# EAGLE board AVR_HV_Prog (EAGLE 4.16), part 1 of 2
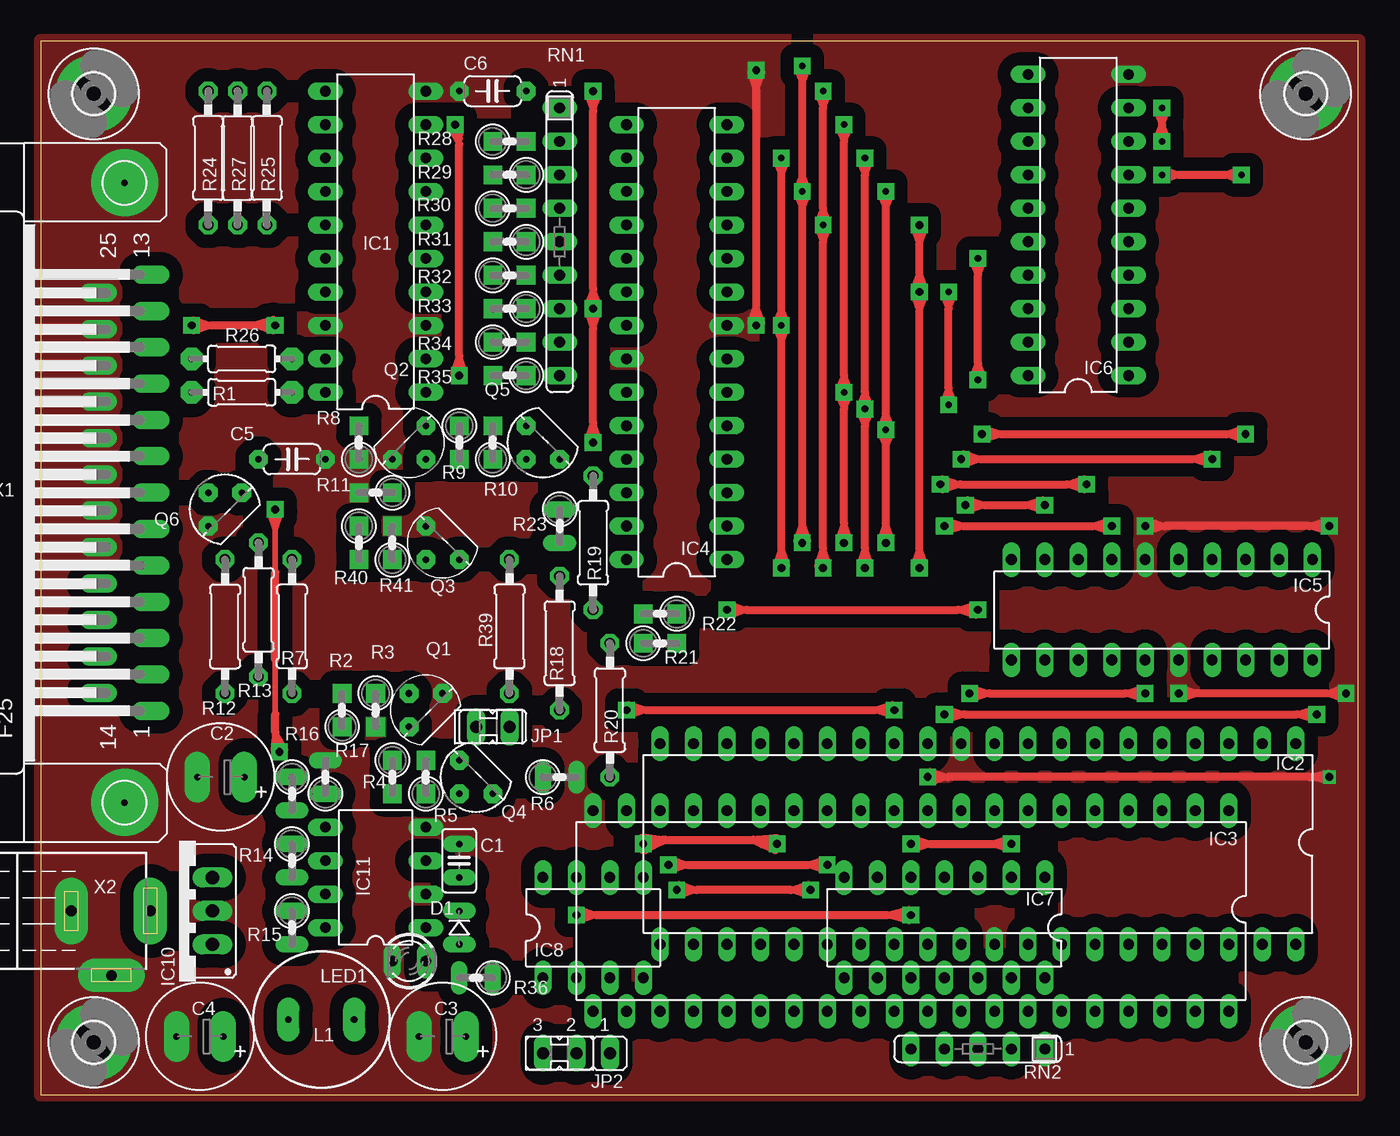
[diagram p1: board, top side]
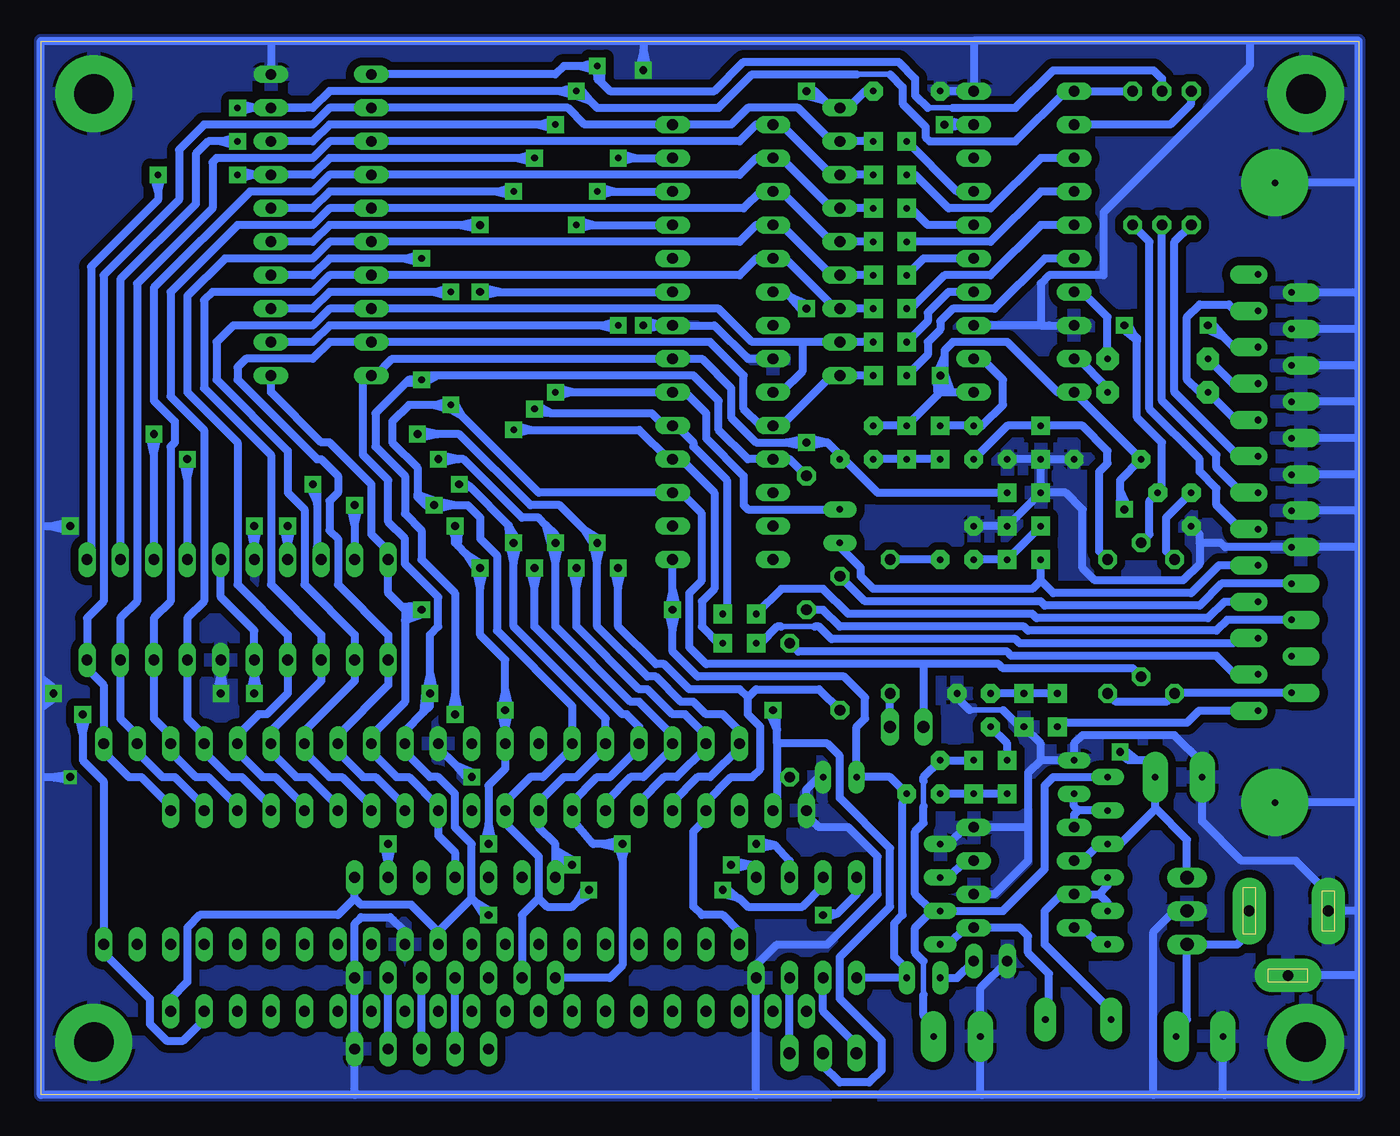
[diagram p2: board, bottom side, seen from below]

Size 100 x 80 mm. Coordinates in mm from the lower left corner, seen from the top.
Outline: 0,0 100,0 100,80 0,80 0,0
Copper layers (1*16): Top 0.035mm / dielectric 1.5mm / Bottom 0.035mm
Design rules "default": minimum track width 12mil, minimum drill 10mil, track to track 10mil, track to pad 12mil, pad to pad 12mil, via to via 12mil, smd to smd 8mil, copper to edge 0mil, drill to drill 8mil, minimum pad ring 10mil, minimum via ring 8mil, stop-mask expansion 4mil, vias tented up to drill 0mil, thermal gap 10mil

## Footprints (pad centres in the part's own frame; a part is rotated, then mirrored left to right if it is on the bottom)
C025-025X050 = drill 0.5 pad 1.27 long: 1 -1.27,0; 2 1.27,0
E3,5-8 = drill 0.5 pad 1.93 long: + -1.778,0; - 1.778,0
C050-024X044 = drill 0.5 pad 1.422 octagon: 1 -2.54,0; 2 2.54,0
D-2.5 = drill 0.5 pad 1.27 long: A 1.27,0; C -1.27,0
3,0-PAD = drill 3 pad 5.842 round: B3,0 0,0
DIL20 = drill 0.813 long: 1 -11.43,-3.81; 2 -8.89,-3.81; 3 -6.35,-3.81; 4 -3.81,-3.81; 5 -1.27,-3.81; 6 1.27,-3.81; 7 3.81,-3.81; 8 6.35,-3.81; 9 8.89,-3.81; 10 11.43,-3.81; 11 11.43,3.81; 12 8.89,3.81; 13 6.35,3.81; 14 3.81,3.81; 15 1.27,3.81; 16 -1.27,3.81; 17 -3.81,3.81; 18 -6.35,3.81; 19 -8.89,3.81; 20 -11.43,3.81
DIL40 = drill 0.813 long: 1 -24.13,-7.62; 2 -21.59,-7.62; 3 -19.05,-7.62; 4 -16.51,-7.62; 5 -13.97,-7.62; 6 -11.43,-7.62; 7 -8.89,-7.62; 8 -6.35,-7.62; 9 -3.81,-7.62; 10 -1.27,-7.62; 11 1.27,-7.62; 12 3.81,-7.62; 13 6.35,-7.62; 14 8.89,-7.62; 15 11.43,-7.62; 16 13.97,-7.62; 17 16.51,-7.62; 18 19.05,-7.62; 19 21.59,-7.62; 20 24.13,-7.62; 21 24.13,7.62; 22 21.59,7.62; 23 19.05,7.62; 24 16.51,7.62; 25 13.97,7.62; 26 11.43,7.62; 27 8.89,7.62; 28 6.35,7.62; 29 3.81,7.62; 30 1.27,7.62; 31 -1.27,7.62; 32 -3.81,7.62; 33 -6.35,7.62; 34 -8.89,7.62; 35 -11.43,7.62; 36 -13.97,7.62; 37 -16.51,7.62; 38 -19.05,7.62; 39 -21.59,7.62; 40 -24.13,7.62
DIL28-3 = drill 0.813 long: 1 -16.51,-3.81; 2 -13.97,-3.81; 3 -11.43,-3.81; 4 -8.89,-3.81; 5 -6.35,-3.81; 6 -3.81,-3.81; 7 -1.27,-3.81; 8 1.27,-3.81; 9 3.81,-3.81; 10 6.35,-3.81; 11 8.89,-3.81; 12 11.43,-3.81; 13 13.97,-3.81; 14 16.51,-3.81; 15 16.51,3.81; 16 13.97,3.81; 17 11.43,3.81; 18 8.89,3.81; 19 6.35,3.81; 20 3.81,3.81; 21 1.27,3.81; 22 -1.27,3.81; 23 -3.81,3.81; 24 -6.35,3.81; 25 -8.89,3.81; 26 -11.43,3.81; 27 -13.97,3.81; 28 -16.51,3.81
DIL14 = drill 0.813 long: 1 -7.62,-3.81; 2 -5.08,-3.81; 3 -2.54,-3.81; 4 0,-3.81; 5 2.54,-3.81; 6 5.08,-3.81; 7 7.62,-3.81; 8 7.62,3.81; 9 5.08,3.81; 10 2.54,3.81; 11 0,3.81; 12 -2.54,3.81; 13 -5.08,3.81; 14 -7.62,3.81
DIL08 = drill 0.813 long: 1 -3.81,-3.81; 2 -1.27,-3.81; 3 1.27,-3.81; 4 3.81,-3.81; 5 3.81,3.81; 6 1.27,3.81; 7 -1.27,3.81; 8 -3.81,3.81
78XXS = drill 1.016 long: GND 0,-2.54; IN -2.54,-2.54; OUT 2.54,-2.54
DIL-08 = drill 0.813 long: 1 -3.81,-3.81; 2 -1.27,-3.81; 3 1.27,-3.81; 4 3.81,-3.81; 5 3.81,3.81; 6 1.27,3.81; 7 -1.27,3.81; 8 -3.81,3.81
JP1 = drill 0.914 long: 1 0,-1.27; 2 0,1.27
JP2 = drill 0.914 long: 1 -2.54,0; 2 0,0; 3 2.54,0
BS11 = drill 0.5 pad 1.676 long: 1 -2.5,0; 2 2.5,0
LED3MM = drill 0.813 pad 1.27 long: A -1.27,0; K 1.27,0
TO92 = drill 0.5 pad 1.422 octagon: 1 1.27,1.27; 2 -1.27,1.27; 3 -1.27,-1.27
0204/7 = drill 0.5 pad 1.676 octagon: 1 -3.81,0; 2 3.81,0
0207/2V = drill 0.5 pad 1.422 square: 1 -1.27,0; 2 1.27,0
0207V = drill 0.5 pad 1.27 long: 1 -1.27,0; 2 1.27,0
0207/10 = drill 0.813 pad 1.422 octagon: 1 -5.08,0; 2 5.08,0
SIL9 = drill 0.813 long: 1 -10.16,0; 2 -7.62,0; 3 -5.08,0; 4 -2.54,0; 5 0,0; 6 2.54,0; 7 5.08,0; 8 7.62,0; 9 10.16,0
SIL5 = drill 0.813 long: 1 -5.08,0; 2 -2.54,0; 3 0,0; 4 2.54,0; 5 5.08,0
F25HP = drill 0.5 pad 1.422 offset: 1 -16.561,-1.27; 2 -13.792,-1.27; 3 -11.049,-1.27; 4 -8.28,-1.27; 5 -5.512,-1.27; 6 -2.769,-1.27; 7 0,-1.27; 8 2.769,-1.27; 9 5.512,-1.27; 10 8.28,-1.27; 11 11.049,-1.27; 12 13.792,-1.27; 13 16.561,-1.27; 14 -15.189,1.27; 15 -12.421,1.27; 16 -9.652,1.27; 17 -6.909,1.27; 18 -4.14,1.27; 19 -1.372,1.27; 20 1.372,1.27; 21 4.14,1.27; 22 6.909,1.27; 23 9.652,1.27; 24 12.421,1.27; 25 15.189,1.27 | drill 0.5 pad 5.08 round: G1 -23.52,0; G2 23.52,0
NEB21R = drill 0.813 pad 2.54 long: + 0,7.35; - 0,1.35; C 4.9,4.4

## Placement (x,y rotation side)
C1  1nF  [C025-025X050]  31.75,17.78 90 top
C2  330µ16V  [E3,5-8]  13.65,24.13 180 top
C3  220µ25V  [E3,5-8]  30.48,4.45 180 top
C4  220µ25V  [E3,5-8]  12.06,4.45 180 top
C5  100n  [C050-024X044]  19.05,48.26 0 top
C6  10n  [C050-024X044]  34.29,76.2 180 top
D1  SB120  [D-2.5]  31.75,12.7 270 top
H1  MOUNT-PAD-ROUND3.0  [3,0-PAD]  4,76 0 top
H2  MOUNT-PAD-ROUND3.0  [3,0-PAD]  4,4 0 top
H3  MOUNT-PAD-ROUND3.0  [3,0-PAD]  96,4 0 top
H4  MOUNT-PAD-ROUND3.0  [3,0-PAD]  96,76 0 top
IC1  74HC299N  [DIL20]  25.4,64.77 90 top
IC2  [DIL40]  71.12,19.05 180 top
IC3  [DIL40]  66.04,13.97 180 top
IC4  [DIL28-3]  48.26,57.15 90 top
IC5  [DIL20]  85.09,36.83 180 top
IC6  [DIL20]  78.74,66.04 90 top
IC7  [DIL14]  68.58,12.7 180 top
IC8  [DIL08]  41.91,12.7 0 top
IC10  LM2940-5  [78XXS]  10.48,13.97 90 top
IC11  MC34063AP  [DIL-08]  25.4,16.51 90 top
J1  [JUMP]  33.97,27.94 90 top
J2  [JUMP]  39.37,3.17 90 top
JP1  DIP8/14  [JP1]  34.29,27.94 270 top
JP2  [JP2]  40.64,3.17 180 top
L1  330µH  [BS11]  21.27,5.71 0 top
LED1  [LED3MM]  27.94,10.16 180 top
Q1  BC547  [TO92]  29.21,29.21 0 top
Q2  BC547  [TO92]  27.94,49.53 180 top
Q3  BC547  [TO92]  30.48,41.91 90 top
Q4  BC557  [TO92]  33.02,24.13 90 top
Q5  BC557  [TO92]  38.1,49.53 90 top
Q6  BC557  [TO92]  13.97,44.45 0 top
R1  1k  [0204/7]  15.24,53.34 180 top
R2  10k  [0207/2V]  22.86,29.21 90 top
R3  10k  [0207/2V]  25.4,29.21 270 top
R4  10k  [0207/2V]  26.67,24.13 270 top
R5  10k  [0207/2V]  29.21,24.13 90 top
R6  4k7  [0207V]  39.37,24.13 0 top
R7  10k  [0207/10]  19.05,35.56 90 top
R8  10k  [0207/2V]  24.13,49.53 90 top
R9  2k2  [0207/2V]  31.75,49.53 270 top
R10  47k  [0207/2V]  34.29,49.53 90 top
R11  680R  [0207/2V]  25.4,45.72 180 top
R12  10k  [0207/10]  13.97,35.56 270 top
R13  100R  [0207/10]  16.51,36.83 270 top
R14  0R22  [0207V]  19.05,17.78 270 top
R15  180R  [0207V]  19.05,12.7 270 top
R16  24k  [0207V]  19.05,22.86 270 top
R17  2k7  [0207V]  21.59,24.13 90 top
R18  1k  [0207/10]  39.37,34.29 270 top
R19  1k  [0207/10]  41.91,41.91 90 top
R20  1k  [0207/10]  43.18,29.21 270 top
R21  1k  [0207/2V]  46.99,34.29 0 top
R22  1k  [0207/2V]  46.99,36.51 180 top
R23  1k  [0207V]  39.37,43.18 270 top
R24  1k  [0207/10]  12.7,71.12 90 top
R25  1k  [0207/10]  17.14,71.12 90 top
R26  100R  [0204/7]  15.24,55.88 0 top
R27  1k  [0207/10]  14.92,71.12 270 top
R28  1k  [0207/2V]  35.56,72.39 0 top
R29  1k  [0207/2V]  35.56,69.85 180 top
R30  1k  [0207/2V]  35.56,67.31 0 top
R31  1k  [0207/2V]  35.56,64.77 180 top
R32  1k  [0207/2V]  35.56,62.23 0 top
R33  1k  [0207/2V]  35.56,59.69 180 top
R34  1k  [0207/2V]  35.56,57.15 0 top
R35  1k  [0207/2V]  35.56,54.61 180 top
R36  4k7  [0207V]  33.02,8.89 180 top
R39  100R  [0207/10]  35.56,35.56 90 top
R40  10k  [0207/2V]  24.13,41.91 270 top
R41  10k  [0207/2V]  26.67,41.91 90 top
RN1  100k  [SIL9]  39.37,64.77 270 top
RN2  4*1k  [SIL5]  71.12,3.49 180 top
X1  [F25HP]  6.35,45.72 90 top
X2  +6...24V  [NEB21R]  0.95,13.97 270 top

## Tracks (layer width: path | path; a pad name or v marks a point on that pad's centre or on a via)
+12V
  Bottom 0.406: 33.02,21.91 33.02,23.81 | 33.02,7.62 33.02,10.16
  Bottom 0.61: R16.1 23.18,24.13 23.81,23.5 23.81,17.14 26.99,13.97 D1.C 32.38,13.97 | 32.38,13.97 33.66,12.7 33.66,10.79 33.02,10.16 | 33.02,21.91 33.02,20.64 33.66,20 33.66,15.24 32.38,13.97 | 33.02,23.81 33.02,24.13 Q4.1 R5.2 | 33.02,7.62 33.02,6.03 32.38,5.4 32.38,4.45 C3.+
/ACK
  Bottom 0.61: X1.10 9.55,54 R26.1
/AUTOFD
  Bottom 0.61: R18.1 37.47,37.47 24.13,37.47 23.81,37.15 12.06,37.15 10.4,38.81 X1.17
/INIT
  Bottom 0.61: R19.1 40.64,36.83 39.37,35.56 25.4,35.56 25.08,35.24 10.79,35.24 9.97,36.07 X1.16
/OE  (via drill 0.5 pad 1.27, 0.6 pad 1.27)
  Top 0.406: v64.14,50.48 64.14,51.73 | 64.14,67.33 v64.14,68.58 | v64.14,41.91 64.14,43.41 | 64.14,49.23 v64.14,50.48 | v68.26,46.35 69.76,46.35 | 77.88,46.35 v79.38,46.35 | v47.62,17.46 49.12,17.46 | 58.19,17.46 v59.69,17.46 | 64.14,67.33 64.58,68.39 | v64.14,68.58 64.58,68.39 | 64.14,67.33 63.69,68.39 | v64.14,68.58 63.69,68.39 | 64.14,67.33 64.58,68.39 | 64.14,67.33 63.69,68.39 | 64.14,67.33 64.58,68.39 | v64.14,68.58 64.58,68.39 | 64.14,67.33 63.69,68.39 | v64.14,68.58 63.69,68.39 | 64.14,51.73 63.69,50.67 | v64.14,50.48 63.69,50.67 | 64.14,51.73 64.58,50.67 | v64.14,50.48 64.58,50.67 | 64.14,49.23 64.58,50.3 | v64.14,50.48 64.58,50.3 | 64.14,49.23 63.69,50.3 | v64.14,50.48 63.69,50.3 | 63.69,50.67 64.14,51.73 | 64.58,50.67 64.14,51.73 | 64.14,51.73 63.69,50.67 | v64.14,50.48 63.69,50.67 | 64.14,51.73 64.58,50.67 | v64.14,50.48 64.58,50.67 | 64.14,49.23 64.58,50.3 | 64.14,49.23 63.69,50.3 | 64.14,49.23 64.58,50.3 | v64.14,50.48 64.58,50.3 | 64.14,49.23 63.69,50.3 | v64.14,50.48 63.69,50.3 | 64.14,43.41 63.68,42.06 | v64.14,41.91 63.68,42.06 | 64.14,43.41 64.59,42.06 | v64.14,41.91 64.59,42.06 | 63.68,42.06 64.14,43.41 | 64.59,42.06 64.14,43.41 | 64.14,43.41 63.68,42.06 | v64.14,41.91 63.68,42.06 | 64.14,43.41 64.59,42.06 | v64.14,41.91 64.59,42.06 | 77.88,46.35 79.22,45.9 | v79.38,46.35 79.22,45.9 | 77.88,46.35 79.22,46.81 | v79.38,46.35 79.22,46.81 | 77.88,46.35 79.22,45.9 | 77.88,46.35 79.22,46.81 | 77.88,46.35 79.22,45.9 | v79.38,46.35 79.22,45.9 | 77.88,46.35 79.22,46.81 | v79.38,46.35 79.22,46.81 | 69.76,46.35 68.42,46.81 | v68.26,46.35 68.42,46.81 | 69.76,46.35 68.42,45.9 | v68.26,46.35 68.42,45.9 | 69.76,46.35 68.42,46.81 | 69.76,46.35 68.42,45.9 | 68.42,46.81 69.76,46.35
  Top 0.406: v68.26,46.35 68.42,46.81 | 68.42,45.9 69.76,46.35 | v68.26,46.35 68.42,45.9 | 49.12,17.46 47.78,17.92 | v47.62,17.46 47.78,17.92 | 49.12,17.46 47.78,17.01 | v47.62,17.46 47.78,17.01 | 49.12,17.46 47.78,17.92 | 49.12,17.46 47.78,17.01 | 47.78,17.92 49.12,17.46 | v47.62,17.46 47.78,17.92 | 47.78,17.01 49.12,17.46 | v47.62,17.46 47.78,17.01 | 58.19,17.46 59.53,17.01 | v59.69,17.46 59.53,17.01 | 58.19,17.46 59.53,17.92 | v59.69,17.46 59.53,17.92 | 58.19,17.46 59.53,17.01 | 58.19,17.46 59.53,17.92 | 58.19,17.46 59.53,17.01 | v59.69,17.46 59.53,17.01 | 58.19,17.46 59.53,17.92 | v59.69,17.46 59.53,17.92 | 64.54,68.43 64.14,67.33 | 64.14,67.33 | 63.73,68.43 64.14,67.33 | 64.14,67.33 64.54,68.43 | 64.54,68.43 v64.14,68.58 | 64.14,67.33 63.73,68.43 | 63.73,68.43 v64.14,68.58 | 64.14,67.33 64.54,68.43 | v64.14,68.58 64.54,68.43 | 64.14,67.33 63.73,68.43 | v64.14,68.58 63.73,68.43 | 64.14,51.73 | 63.73,50.63 64.14,51.73 | 63.73,50.63 | v64.14,50.48 63.73,50.63 | 64.54,50.63 64.14,51.73 | 64.54,50.63 | v64.14,50.48 64.54,50.63 | 63.73,50.63 64.14,51.73 | 64.54,50.63 64.14,51.73 | 63.73,50.63 64.14,51.73 | v64.14,50.48 63.73,50.63 | 64.54,50.63 64.14,51.73 | v64.14,50.48 64.54,50.63 | 64.54,50.33 64.14,49.23 | 64.14,49.23 | 63.73,50.33 64.14,49.23 | 64.14,49.23 64.54,50.33 | 64.54,50.33 v64.14,50.48 | 64.14,49.23 63.73,50.33 | 63.73,50.33 v64.14,50.48 | 64.14,49.23 64.54,50.33 | v64.14,50.48 64.54,50.33 | 64.14,49.23 63.73,50.33 | v64.14,50.48 63.73,50.33 | 63.72,42.03 64.14,43.41 | 63.72,42.03 | 64.14,43.41 | 63.72,42.03 64.14,43.41 | 63.72,42.03 | v64.14,41.91 63.72,42.03 | 64.55,42.03 64.14,43.41 | 63.72,42.03 64.14,43.41 | v64.14,41.91 63.72,42.03 | 64.55,42.03 64.14,43.41 | 64.55,42.03
  Top 0.406: v64.14,41.91 64.55,42.03 | 63.72,42.03 64.14,43.41 | v64.14,41.91 63.72,42.03 | 64.55,42.03 64.14,43.41 | v64.14,41.91 64.55,42.03 | 79.25,45.94 77.88,46.35 | 79.25,45.94 | 77.88,46.35 | 77.88,46.35 79.25,45.94 | 79.25,45.94 | v79.38,46.35 79.25,45.94 | 79.25,46.77 77.88,46.35 | 77.88,46.35 79.25,45.94 | 79.25,45.94 v79.38,46.35 | 77.88,46.35 79.25,46.77 | 79.25,46.77 | 79.25,46.77 v79.38,46.35 | 77.88,46.35 79.25,45.94 | v79.38,46.35 79.25,45.94 | 79.25,46.77 77.88,46.35 | 79.25,46.77 v79.38,46.35 | 68.39,46.77 69.76,46.35 | 68.39,46.77 | 68.39,46.77 69.76,46.35 | v68.26,46.35 68.39,46.77 | 69.76,46.35 | 68.39,45.94 69.76,46.35 | 68.39,45.94 | v68.26,46.35 68.39,45.94 | 68.39,46.77 69.76,46.35 | 68.39,45.94 69.76,46.35 | v68.26,46.35 68.39,45.94 | 68.39,46.77 69.76,46.35 | v68.26,46.35 68.39,46.77 | 68.39,45.94 69.76,46.35 | v68.26,46.35 68.39,45.94 | 47.75,17.88 49.12,17.46 | 47.75,17.88 | 47.75,17.88 49.12,17.46 | v47.62,17.46 47.75,17.88 | 49.12,17.46 | 47.75,17.05 49.12,17.46 | 47.75,17.05 | v47.62,17.46 47.75,17.05 | 47.75,17.88 49.12,17.46 | 47.75,17.05 49.12,17.46 | v47.62,17.46 47.75,17.05 | 47.75,17.88 49.12,17.46 | v47.62,17.46 47.75,17.88 | 47.75,17.05 49.12,17.46 | v47.62,17.46 47.75,17.05 | 59.57,17.05 58.19,17.46 | 59.57,17.05 | 58.19,17.46 | 58.19,17.46 59.57,17.05 | 59.57,17.05 | v59.69,17.46 59.57,17.05 | 59.57,17.88 58.19,17.46 | 58.19,17.46 59.57,17.05 | 59.57,17.05 v59.69,17.46 | 58.19,17.46 59.57,17.88 | 59.57,17.88 | 59.57,17.88 v59.69,17.46 | 58.19,17.46 59.57,17.05 | v59.69,17.46 59.57,17.05 | 59.57,17.88 58.19,17.46 | 59.57,17.88 v59.69,17.46
  Top 0.61: 64.14,51.73 | 64.14,51.73 64.14,67.33 | 64.14,67.33 | 64.14,43.41 | 64.14,43.41 64.14,49.23 | 69.76,46.35 | 69.76,46.35 77.88,46.35 | 77.88,46.35 | 49.12,17.46 | 49.12,17.46 58.19,17.46 | 58.19,17.46
  Bottom 0.61: IC6.6 79.38,67.31 78.11,68.58 65.39,68.58 | v64.14,68.58 65.39,68.58 | v64.14,50.48 62.88,50.48 | 62.88,50.48 54.61,50.48 52.39,48.26 IC4.4 51.44,48.26 48.9,45.72 48.9,38.42 49.85,37.47 49.85,35.56 48.58,34.29 R21.2 | v79.38,46.35 79.06,46.04 79.06,44.89 | 79.06,44.89 79.06,41.59 78.74,41.27 IC5.8 | 64.51,43.24 64.14,42.55 v64.14,41.91 | 64.51,43.24 67.37,46.1 | 67.37,46.1 67.94,46.35 v68.26,46.35 | 64.14,40.41 64.14,35.56 57.15,28.57 IC2.16 57.15,26.35 59.37,24.13 60.33,24.13 62.23,22.23 IC3.12 62.23,20.32 60.96,19.05 60.96,18.58 | 64.14,40.41 v64.14,41.91 | IC8.5 45.72,17.14 46.12,17.46 | 46.12,17.46 v47.62,17.46 | 60.96,17.78 60.96,16.98 | 60.96,16.98 IC7.7 | 60.96,17.78 60.96,18.58 | v59.69,17.46 60.96,17.78 | 65.39,68.58 64.22,68.9 v64.14,68.58 | 65.39,68.58 64.22,68.26 v64.14,68.58 | 62.88,50.48 64.05,50.16 v64.14,50.48 | 62.88,50.48 64.05,50.8 v64.14,50.48 | 64.51,43.24 63.88,42.12 v64.14,41.91 | 64.51,43.24 64.45,41.83 v64.14,41.91 | 64.14,40.41 64.46,41.84 v64.14,41.91 | 64.14,40.41 63.81,41.84 v64.14,41.91 | 79.06,44.89 79.67,46.22 v79.38,46.35 | 79.06,44.89 79.05,46.35 v79.38,46.35 | 67.37,46.1 68.39,46.05 v68.26,46.35 | 67.37,46.1 68.01,46.57 v68.26,46.35 | 46.12,17.46 47.55,17.14 v47.62,17.46 | 46.12,17.46 47.55,17.79 v47.62,17.46 | 60.96,16.98 59.92,17.7 v59.69,17.46 | 60.96,16.98 59.58,17.15 v59.69,17.46 | 60.96,18.58 59.58,17.77 v59.69,17.46 | 60.96,18.58 59.92,17.23 v59.69,17.46
/RESET  (via drill 0.6 pad 1.27)
  Top 0.406: v52.07,36.83 53.57,36.83 | 69.62,36.83 v71.12,36.83 | 53.57,36.83 52.23,37.29 | v52.07,36.83 52.23,37.29 | 53.57,36.83 52.23,36.37 | v52.07,36.83 52.23,36.37 | 53.57,36.83 52.23,37.29 | 53.57,36.83 52.23,36.37 | 52.23,37.29 53.57,36.83 | v52.07,36.83 52.23,37.29 | 52.23,36.37 53.57,36.83 | v52.07,36.83 52.23,36.37 | 69.62,36.83 70.97,36.37 | v71.12,36.83 70.97,36.37 | 69.62,36.83 70.97,37.29 | v71.12,36.83 70.97,37.29 | 69.62,36.83 70.97,36.37 | 69.62,36.83 70.97,37.29 | 69.62,36.83 70.97,36.37 | v71.12,36.83 70.97,36.37 | 69.62,36.83 70.97,37.29 | v71.12,36.83 70.97,37.29 | 52.19,37.24 53.57,36.83 | 52.19,37.24 | 52.19,37.24 53.57,36.83 | v52.07,36.83 52.19,37.24 | 53.57,36.83 | 52.19,36.42 53.57,36.83 | 52.19,36.42 | v52.07,36.83 52.19,36.42 | 52.19,37.24 53.57,36.83 | 52.19,36.42 53.57,36.83 | v52.07,36.83 52.19,36.42 | 52.19,37.24 53.57,36.83 | v52.07,36.83 52.19,37.24 | 52.19,36.42 53.57,36.83 | v52.07,36.83 52.19,36.42 | 71,36.42 69.62,36.83 | 71,36.42 | 69.62,36.83 | 69.62,36.83 71,36.42 | 71,36.42 | v71.12,36.83 71,36.42 | 71,37.24 69.62,36.83 | 69.62,36.83 71,36.42 | 71,36.42 v71.12,36.83 | 69.62,36.83 71,37.24 | 71,37.24 | 71,37.24 v71.12,36.83 | 69.62,36.83 71,36.42 | v71.12,36.83 71,36.42 | 71,37.24 69.62,36.83 | 71,37.24 v71.12,36.83
  Top 0.61: 53.57,36.83 | 53.57,36.83 69.62,36.83 | 69.62,36.83
  Bottom 0.61: IC6.1 82.55,53.34 78.74,49.53 78.11,49.53 74.93,46.35 74.93,42.55 73.66,41.27 IC5.10 73.66,38.1 72.61,37.05 | v52.07,36.83 52.07,38.33 | 52.07,38.33 IC4.1 | v71.12,36.83 72.39,36.83 | 72.39,36.83 72.61,37.05 | 72.39,36.83 72.39,36.03 | 72.39,36.03 72.39,29.84 74.93,27.3 IC2.9 74.93,26.04 73.03,24.13 72.07,24.13 69.85,21.91 IC3.9 69.85,19.68 68.58,18.41 IC7.4 | 52.07,35.33 52.07,33.66 50.16,31.75 39.05,31.75 37.47,30.16 37.47,28.57 38.1,27.94 R6.1 35.56,24.13 Q4.3 34.29,22.54 34.61,22.23 34.61,13.65 35.24,13.02 35.24,10.48 34.29,9.53 R36.1 IC8.1 | 52.07,35.33 v52.07,36.83 | 52.07,38.33 51.75,36.9 v52.07,36.83 | 52.07,38.33 52.39,36.9 v52.07,36.83 | 52.07,35.33 52.39,36.76 v52.07,36.83 | 52.07,35.33 51.75,36.76 v52.07,36.83 | 72.61,37.05 71.15,37.16 v71.12,36.83 | 72.61,37.05 71.24,36.52 v71.12,36.83 | 72.39,36.03 71.35,37.06 v71.12,36.83 | 72.39,36.03 71.01,36.52 v71.12,36.83
/SELIN
  Bottom 0.61: X1.14 13.92,30.53 R12.2 14.61,29.84 18.41,29.84 R7.1
/STB
  Bottom 0.61: X1.1 12.12,29.16 13.02,28.26 22.54,28.26 R2.1
/WR  (via drill 0.5 pad 1.27, 0.6 pad 1.27)
  Top 0.406: v62.55,52.07 62.55,53.32 | 62.55,69.87 v62.55,71.12 | v85.09,69.85 86.34,69.85 | 89.87,69.85 v91.12,69.85 | v62.55,40.01 62.55,41.51 | 62.55,50.82 v62.55,52.07 | 62.55,53.32 62.1,52.26 | v62.55,52.07 62.1,52.26 | 62.55,53.32 62.99,52.26 | v62.55,52.07 62.99,52.26 | 62.55,50.82 62.99,51.88 v62.55,52.07 | 62.55,50.82 62.1,51.88 v62.55,52.07 | 62.1,52.26 62.55,53.32 | 62.99,52.26 62.55,53.32 | 62.55,53.32 62.1,52.26 | v62.55,52.07 62.1,52.26 | 62.55,53.32 62.99,52.26 | v62.55,52.07 62.99,52.26 | 62.55,50.82 62.99,51.88 | 62.55,50.82 62.1,51.88 | 62.55,50.82 62.99,51.88 | v62.55,52.07 62.99,51.88 | 62.55,50.82 62.1,51.88 | v62.55,52.07 62.1,51.88 | 62.55,69.87 62.99,70.93 v62.55,71.12 | 62.55,69.87 62.1,70.93 v62.55,71.12 | 62.55,69.87 62.99,70.93 | 62.55,69.87 62.1,70.93 | 62.55,69.87 62.99,70.93 | v62.55,71.12 62.99,70.93 | 62.55,69.87 62.1,70.93 | v62.55,71.12 62.1,70.93 | 89.87,69.85 90.94,69.41 | v91.12,69.85 90.94,69.41 | 89.87,69.85 90.94,70.3 | v91.12,69.85 90.94,70.3 | 89.87,69.85 90.94,69.41 | 89.87,69.85 90.94,70.3 | 89.87,69.85 90.94,69.41 | v91.12,69.85 90.94,69.41 | 89.87,69.85 90.94,70.3 | v91.12,69.85 90.94,70.3 | 86.34,69.85 85.28,70.3 | v85.09,69.85 85.28,70.3 | 86.34,69.85 85.28,69.41 | v85.09,69.85 85.28,69.41 | 86.34,69.85 85.28,70.3 | 86.34,69.85 85.28,69.41 | 85.28,70.3 86.34,69.85 | v85.09,69.85 85.28,70.3 | 85.28,69.41 86.34,69.85 | v85.09,69.85 85.28,69.41 | 62.55,41.51 62.09,40.16 | v62.55,40.01 62.09,40.16 | 62.55,41.51 63,40.16 | v62.55,40.01 63,40.16 | 62.09,40.16 62.55,41.51 | 63,40.16 62.55,41.51 | 62.55,41.51 62.09,40.16 | v62.55,40.01 62.09,40.16 | 62.55,41.51 63,40.16 | v62.55,40.01 63,40.16 | 62.55,53.32 | 62.14,52.22 62.55,53.32 | 62.14,52.22
  Top 0.406: v62.55,52.07 62.14,52.22 | 62.95,52.22 62.55,53.32 | 62.95,52.22 | v62.55,52.07 62.95,52.22 | 62.14,52.22 62.55,53.32 | 62.95,52.22 62.55,53.32 | 62.14,52.22 62.55,53.32 | v62.55,52.07 62.14,52.22 | 62.95,52.22 62.55,53.32 | v62.55,52.07 62.95,52.22 | 62.95,51.92 62.55,50.82 | 62.55,50.82 | 62.14,51.92 62.55,50.82 | 62.55,50.82 62.95,51.92 | 62.95,51.92 v62.55,52.07 | 62.55,50.82 62.14,51.92 | 62.14,51.92 v62.55,52.07 | 62.55,50.82 62.95,51.92 | v62.55,52.07 62.95,51.92 | 62.55,50.82 62.14,51.92 | v62.55,52.07 62.14,51.92 | 62.95,70.97 62.55,69.87 | 62.55,69.87 | 62.14,70.97 62.55,69.87 | 62.55,69.87 62.95,70.97 | 62.95,70.97 v62.55,71.12 | 62.55,69.87 62.14,70.97 | 62.14,70.97 v62.55,71.12 | 62.55,69.87 62.95,70.97 | v62.55,71.12 62.95,70.97 | 62.55,69.87 62.14,70.97 | v62.55,71.12 62.14,70.97 | 89.87,69.85 | 90.97,69.44 89.87,69.85 | 90.97,69.44 | v91.12,69.85 90.97,69.44 | 90.97,70.25 89.87,69.85 | 90.97,70.25 | 90.97,70.25 v91.12,69.85 | 89.87,69.85 90.97,69.44 | 89.87,69.85 90.97,70.25 | 90.97,69.44 89.87,69.85 | 90.97,69.44 v91.12,69.85 | 90.97,70.25 89.87,69.85 | 90.97,70.25 v91.12,69.85 | 85.24,70.25 86.34,69.85 | 86.34,69.85 | 85.24,69.44 86.34,69.85 | 85.24,70.25 86.34,69.85 | v85.09,69.85 85.24,70.25 | 85.24,69.44 86.34,69.85 | v85.09,69.85 85.24,69.44 | 85.24,70.25 86.34,69.85 | v85.09,69.85 85.24,70.25 | 85.24,69.44 86.34,69.85 | v85.09,69.85 85.24,69.44 | 62.13,40.13 62.55,41.51 | 62.13,40.13 | 62.55,41.51 | 62.13,40.13 62.55,41.51 | 62.13,40.13 | v62.55,40.01 62.13,40.13 | 62.96,40.13 62.55,41.51 | 62.13,40.13 62.55,41.51 | v62.55,40.01 62.13,40.13 | 62.96,40.13 62.55,41.51 | 62.96,40.13 | v62.55,40.01 62.96,40.13 | 62.13,40.13 62.55,41.51 | v62.55,40.01 62.13,40.13
  Top 0.406: 62.96,40.13 62.55,41.51 | v62.55,40.01 62.96,40.13
  Top 0.61: v45.72,19.05 46.9,19.37 | 54.06,19.37 54.4,19.31 | 54.4,19.31 v55.88,19.05 | 62.55,53.32 | 62.55,53.32 62.55,69.87 | 62.55,69.87 | 86.34,69.85 | 86.34,69.85 89.87,69.85 | 62.55,41.51 | 62.55,41.51 62.55,50.82 | 62.55,50.82 | 46.9,19.37 45.88,19.51 v45.72,19.05 | 46.9,19.37 45.88,18.59 | v45.72,19.05 45.88,18.59 | 46.9,19.37 45.56,19.51 | 46.9,19.37 45.88,18.59 | 45.56,19.51 47.22,19.37 45.88,18.59 | v45.72,19.05 45.56,19.51 | v45.72,19.05 45.88,18.59 | 54.39,19.21 55.73,18.59 | 55.73,18.59 v55.88,19.05 | 46.9,19.37 47.4,19.37 | 47.4,19.37 54.06,19.37 | 54.06,19.37 55.73,19.51 | 55.73,19.51 v55.88,19.05 | 55.73,18.59 54.7,19.05 55.73,19.51 | 54.06,19.37 54.39,19.21 | 54.39,19.21 55.73,18.59 | 55.73,18.59 v55.88,19.05 | 54.06,19.37 54.42,19.4 | 54.42,19.4 55.73,19.51 | 55.73,19.51 v55.88,19.05 | 47.4,19.37 46.01,19.37 v45.72,19.05 | 47.4,19.37 45.66,18.62 v45.72,19.05 | 54.4,19.31 55.69,18.66 v55.88,19.05 | 54.4,19.31 55.83,19.48 v55.88,19.05 | 54.39,19.21 55.71,18.65 | 55.71,18.65 | 54.39,19.21 55.71,18.65 | 55.71,18.65 v55.88,19.05 | 54.39,19.21 55.8,19.48 v55.88,19.05 | 54.42,19.4 55.66,18.68 v55.88,19.05 | 54.42,19.4 55.85,19.48 v55.88,19.05
  Bottom 0.61: v62.55,52.07 61.3,51.75 | 61.3,51.75 53.66,51.75 52.7,50.8 IC4.5 51.75,50.8 50.48,49.53 50.48,49.21 47.94,46.67 47.94,36.83 R22.1 | v62.55,71.12 63.8,71.12 | 63.8,71.12 78.11,71.12 79.38,69.85 IC6.7 83.84,69.85 | IC5.1 96.2,40.96 96.2,62.87 91.12,67.94 91.12,68.6 | v91.12,69.85 91.12,68.6 | 83.84,69.85 v85.09,69.85 | 62.55,38.51 62.55,35.56 55.88,28.89 55.56,28.89 54.61,27.94 IC2.17 54.61,26.35 56.83,24.13 57.78,24.13 59.69,22.23 IC3.13 59.69,20.95 58.1,19.05 57.38,19.05 | 62.55,38.51 v62.55,40.01 | IC7.8 56.83,8.89 55.88,9.84 55.88,17.87 | IC8.6 43.18,17.78 44.24,18.94 | 44.24,18.94 v45.72,19.05 | v55.88,19.05 57.38,19.05 | v55.88,19.05 55.88,17.87 | 61.3,51.75 62.46,51.75 v62.55,52.07 | 61.3,51.75 62.46,52.39 v62.55,52.07 | 63.8,71.12 62.63,71.44 v62.55,71.12 | 63.8,71.12 62.63,70.8 v62.55,71.12 | 91.12,68.6 91.44,69.76 v91.12,69.85 | 91.12,68.6 90.8,69.76 v91.12,69.85 | 83.84,69.85 85,69.53 v85.09,69.85 | 83.84,69.85 85,70.17 v85.09,69.85 | 62.55,38.51 62.87,39.93 v62.55,40.01 | 62.55,38.51 62.23,39.93 v62.55,40.01 | 44.24,18.94 45.36,19.23 v45.72,19.05 | 44.24,18.94 45.23,18.77 v45.72,19.05 | 57.38,19.05 55.95,19.37 v55.88,19.05 | 57.38,19.05 55.95,18.73 v55.88,19.05 | 55.88,17.87 56.2,18.98 v55.88,19.05 | 55.88,17.87 55.56,18.98 v55.88,19.05
BS1  (via drill 0.5 pad 1.27, 0.6 pad 1.27)
  Top 0.406: v60.96,53.34 60.96,54.59 | 60.96,72.41 v60.96,73.66 | v69.85,48.26 71.35,48.26 | 87.4,48.26 v88.9,48.26 | v60.96,41.91 60.96,43.41 | 60.96,52.09 v60.96,53.34 | 60.96,72.41 61.41,73.47 | v60.96,73.66 61.41,73.47 | 60.96,72.41 60.52,73.47 | v60.96,73.66 60.52,73.47 | 60.96,72.41 61.41,73.47 | 60.96,72.41 60.52,73.47 | 60.96,72.41 61.41,73.47 | v60.96,73.66 61.41,73.47 | 60.96,72.41 60.52,73.47 | v60.96,73.66 60.52,73.47 | 60.96,54.59 60.52,53.53 | v60.96,53.34 60.52,53.53 | 60.96,54.59 61.41,53.53 | v60.96,53.34 61.41,53.53 | 60.96,52.09 61.41,53.15 | v60.96,53.34 61.41,53.15 | 60.96,52.09 60.52,53.15 | v60.96,53.34 60.52,53.15 | 60.52,53.53 60.96,54.59 | 61.41,53.53 60.96,54.59 | 60.96,54.59 60.52,53.53 | v60.96,53.34 60.52,53.53 | 60.96,54.59 61.41,53.53 | v60.96,53.34 61.41,53.53 | 60.96,52.09 61.41,53.15 | 60.96,52.09 60.52,53.15 | 60.96,52.09 61.41,53.15 | v60.96,53.34 61.41,53.15 | 60.96,52.09 60.52,53.15 | v60.96,53.34 60.52,53.15 | 87.4,48.26 88.75,47.8 | v88.9,48.26 88.75,47.8 | 87.4,48.26 88.75,48.72 | v88.9,48.26 88.75,48.72 | 87.4,48.26 88.75,47.8 | 87.4,48.26 88.75,48.72 | 87.4,48.26 88.75,47.8 | v88.9,48.26 88.75,47.8 | 87.4,48.26 88.75,48.72 | v88.9,48.26 88.75,48.72 | 71.35,48.26 70,48.72 | v69.85,48.26 70,48.72 | 71.35,48.26 70,47.8 | v69.85,48.26 70,47.8 | 71.35,48.26 70,48.72 | 71.35,48.26 70,47.8 | 70,48.72 71.35,48.26 | v69.85,48.26 70,48.72 | 70,47.8 71.35,48.26 | v69.85,48.26 70,47.8 | 60.96,43.41 60.5,42.06 | v60.96,41.91 60.5,42.06 | 60.96,43.41 61.42,42.06 | v60.96,41.91 61.42,42.06 | 60.5,42.06 60.96,43.41 | 61.42,42.06 60.96,43.41 | 60.96,43.41 60.5,42.06 | v60.96,41.91 60.5,42.06 | 60.96,43.41 61.42,42.06 | v60.96,41.91 61.42,42.06 | 61.37,73.51 60.96,72.41
  Top 0.406: 60.96,72.41 | 60.55,73.51 60.96,72.41 | 60.96,72.41 61.37,73.51 | 61.37,73.51 v60.96,73.66 | 60.96,72.41 60.55,73.51 | 60.55,73.51 v60.96,73.66 | 60.96,72.41 61.37,73.51 | v60.96,73.66 61.37,73.51 | 60.96,72.41 60.55,73.51 | v60.96,73.66 60.55,73.51 | 60.96,54.59 | 60.55,53.49 60.96,54.59 | 60.55,53.49 | v60.96,53.34 60.55,53.49 | 61.37,53.49 60.96,54.59 | 61.37,53.49 | v60.96,53.34 61.37,53.49 | 60.55,53.49 60.96,54.59 | 61.37,53.49 60.96,54.59 | 60.55,53.49 60.96,54.59 | v60.96,53.34 60.55,53.49 | 61.37,53.49 60.96,54.59 | v60.96,53.34 61.37,53.49 | 61.37,53.19 60.96,52.09 | 60.96,52.09 | 60.55,53.19 60.96,52.09 | 60.96,52.09 61.37,53.19 | 61.37,53.19 v60.96,53.34 | 60.96,52.09 60.55,53.19 | 60.55,53.19 v60.96,53.34 | 60.96,52.09 61.37,53.19 | v60.96,53.34 61.37,53.19 | 60.96,52.09 60.55,53.19 | v60.96,53.34 60.55,53.19 | 88.78,47.85 87.4,48.26 | 88.78,47.85 | 87.4,48.26 | 87.4,48.26 88.78,47.85 | 88.78,47.85 | v88.9,48.26 88.78,47.85 | 88.78,48.67 87.4,48.26 | 87.4,48.26 88.78,47.85 | 88.78,47.85 v88.9,48.26 | 87.4,48.26 88.78,48.67 | 88.78,48.67 v88.9,48.26 | 87.4,48.26 88.78,47.85 | v88.9,48.26 88.78,47.85 | 88.78,48.67 87.4,48.26 | 88.78,48.67 v88.9,48.26 | 69.97,48.67 71.35,48.26 | 69.97,48.67 | 69.97,48.67 71.35,48.26 | v69.85,48.26 69.97,48.67 | 71.35,48.26 | 69.97,47.85 71.35,48.26 | 69.97,47.85 | v69.85,48.26 69.97,47.85 | 69.97,48.67 71.35,48.26 | 69.97,47.85 71.35,48.26 | v69.85,48.26 69.97,47.85 | 69.97,48.67 71.35,48.26 | v69.85,48.26 69.97,48.67 | 69.97,47.85 71.35,48.26 | v69.85,48.26 69.97,47.85 | 60.55,42.03 60.96,43.41 | 60.55,42.03 | 60.96,43.41 | 60.55,42.03 60.96,43.41 | 60.55,42.03 | v60.96,41.91 60.55,42.03 | 61.37,42.03 60.96,43.41 | 60.55,42.03 60.96,43.41 | v60.96,41.91 60.55,42.03
  Top 0.406: 61.37,42.03 60.96,43.41 | 61.37,42.03 | v60.96,41.91 61.37,42.03 | 60.55,42.03 60.96,43.41 | v60.96,41.91 60.55,42.03 | 61.37,42.03 60.96,43.41 | v60.96,41.91 61.37,42.03
  Top 0.61: 60.96,54.59 | 60.96,54.59 60.96,72.41 | 60.96,72.41 | 71.35,48.26 | 71.35,48.26 87.4,48.26 | 87.4,48.26 | 60.96,43.41 | 60.96,43.41 60.96,52.09 | 60.96,52.09
  Bottom 0.61: IC6.8 79.38,72.39 78.11,73.66 62.21,73.66 | v60.96,73.66 62.21,73.66 | v60.96,53.34 59.71,53.34 | 59.71,53.34 IC4.6 51.12,53.34 49.53,51.75 49.53,49.85 46.67,46.99 46.67,44.77 46.35,44.45 R23.1 | v88.9,48.26 88.9,46.76 | 88.9,46.76 IC5.4 | 68.35,48.26 67.94,48.26 63.5,43.81 62.23,43.81 61.66,43.24 | 68.35,48.26 v69.85,48.26 | 61.66,43.24 60.96,42.55 v60.96,41.91 | IC3.14 57.15,22.23 55.24,24.13 54.29,24.13 52.07,26.35 IC2.18 52.07,27.3 54.61,29.84 55.24,29.84 60.96,35.56 60.96,40.41 | 60.96,40.41 v60.96,41.91 | 62.21,73.66 61.05,73.98 v60.96,73.66 | 62.21,73.66 61.05,73.34 v60.96,73.66 | 59.71,53.34 60.87,53.02 v60.96,53.34 | 59.71,53.34 60.87,53.66 v60.96,53.34 | 88.9,46.76 89.22,48.19 v88.9,48.26 | 88.9,46.76 88.58,48.19 v88.9,48.26 | 68.35,48.26 69.78,47.94 v69.85,48.26 | 68.35,48.26 69.78,48.58 v69.85,48.26 | 61.66,43.24 60.71,42.12 v60.96,41.91 | 61.66,43.24 61.28,41.83 v60.96,41.91 | 60.96,40.41 61.28,41.84 v60.96,41.91 | 60.96,40.41 60.64,41.84 v60.96,41.91
BS2  (via drill 0.5 pad 1.27, 0.6 pad 1.27)
  Top 0.406: v71.12,54.29 71.12,55.54 | 71.12,62.25 v71.12,63.5 | v68.58,28.89 70.08,28.89 | 95.34,28.89 v96.84,28.89 | 71.12,62.25 71.56,63.31 v71.12,63.5 | 71.12,62.25 70.67,63.31 v71.12,63.5 | 71.12,62.25 71.56,63.31 | 71.12,62.25 70.67,63.31 | 71.12,62.25 71.56,63.31 | v71.12,63.5 71.56,63.31 | 71.12,62.25 70.67,63.31 | v71.12,63.5 70.67,63.31 | 71.12,55.54 70.67,54.48 | v71.12,54.29 70.67,54.48 | 71.12,55.54 71.56,54.48 | v71.12,54.29 71.56,54.48 | 70.67,54.48 71.12,55.54 | 71.56,54.48 71.12,55.54 | 71.12,55.54 70.67,54.48 | v71.12,54.29 70.67,54.48 | 71.12,55.54 71.56,54.48 | v71.12,54.29 71.56,54.48 | 70.08,28.89 68.73,29.35 | v68.58,28.89 68.73,29.35 | 70.08,28.89 68.73,28.44 | v68.58,28.89 68.73,28.44 | 70.08,28.89 68.73,29.35 | 70.08,28.89 68.73,28.44 | 68.73,29.35 70.08,28.89 | v68.58,28.89 68.73,29.35 | 68.73,28.44 70.08,28.89 | v68.58,28.89 68.73,28.44 | 95.34,28.89 96.68,28.44 | v96.84,28.89 96.68,28.44 | 70.08,28.89 | 95.34,28.89 | 95.34,28.89 96.68,29.35 | v96.84,28.89 96.68,29.35 | 95.34,28.89 96.68,28.44 | 95.34,28.89 96.68,29.35 | 95.34,28.89 96.68,28.44 | v96.84,28.89 96.68,28.44 | 95.34,28.89 96.68,29.35 | v96.84,28.89 96.68,29.35 | 71.53,63.35 71.12,62.25 | 71.12,62.25 | 70.72,63.35 71.12,62.25 | 71.12,62.25 71.53,63.35 | 71.53,63.35 v71.12,63.5 | 71.12,62.25 70.72,63.35 | 70.72,63.35 v71.12,63.5 | 71.12,62.25 71.53,63.35 | v71.12,63.5 71.53,63.35 | 71.12,62.25 70.72,63.35 | v71.12,63.5 70.72,63.35 | 71.12,55.54 | 70.72,54.44 71.12,55.54 | 70.72,54.44 | v71.12,54.29 70.72,54.44 | 71.53,54.44 71.12,55.54 | 71.53,54.44 | v71.12,54.29 71.53,54.44 | 70.72,54.44 71.12,55.54 | 71.53,54.44 71.12,55.54 | 70.72,54.44 71.12,55.54 | v71.12,54.29 70.72,54.44 | 71.53,54.44 71.12,55.54
  Top 0.406: v71.12,54.29 71.53,54.44 | 68.7,29.31 70.08,28.89 | 68.7,29.31 | 68.7,29.31 70.08,28.89 | v68.58,28.89 68.7,29.31 | 70.08,28.89 | 68.7,28.48 70.08,28.89 | 68.7,28.48 | v68.58,28.89 68.7,28.48 | 68.7,29.31 70.08,28.89 | 68.7,28.48 70.08,28.89 | v68.58,28.89 68.7,28.48 | 68.7,29.31 70.08,28.89 | v68.58,28.89 68.7,29.31 | 68.7,28.48 70.08,28.89 | v68.58,28.89 68.7,28.48 | 96.71,28.48 95.34,28.89 | 96.71,28.48 | 95.34,28.89 | 95.34,28.89 96.71,28.48 | 96.71,28.48 | v96.84,28.89 96.71,28.48 | 96.71,29.31 95.34,28.89 | 95.34,28.89 96.71,28.48 | 96.71,28.48 v96.84,28.89 | 95.34,28.89 96.71,29.31 | 96.71,29.31 | 96.71,29.31 v96.84,28.89 | 95.34,28.89 96.71,28.48 | v96.84,28.89 96.71,28.48 | 96.71,29.31 95.34,28.89 | 96.71,29.31 v96.84,28.89
  Top 0.61: 71.12,55.54 71.12,62.25 | 71.12,62.25 | 70.08,28.89 95.34,28.89
  Bottom 0.61: IC6.4 79.38,62.23 78.11,63.5 72.37,63.5 | v71.12,63.5 72.37,63.5 | IC3.39 87.63,5.71 89.22,4.13 90.49,4.13 91.76,5.4 91.76,7.3 95.25,10.79 IC2.40 95.25,23.81 96.84,25.4 96.84,27.39 | R19.2 43.18,48.26 | 43.18,48.26 | 43.18,48.26 IC4.25 46.35,48.26 48.58,50.48 48.58,52.7 50.48,54.61 69.91,54.61 | 68.58,30.39 68.58,38.1 71.12,40.64 71.12,42.86 72.39,44.13 72.39,46.99 74.61,49.21 74.61,51.75 72.34,54.02 | 68.58,30.39 v68.58,28.89 | v96.84,28.89 96.84,27.39 | 69.91,54.61 70.8,54.61 v71.12,54.29 | 72.34,54.02 72.07,54.29 v71.12,54.29 | 72.37,63.5 71.21,63.82 v71.12,63.5 | 72.37,63.5 71.21,63.18 v71.12,63.5 | 69.91,54.61 70.95,54.01 v71.12,54.29 | 69.91,54.61 71.12,54.62 v71.12,54.29 | 72.34,54.02 71.27,54.59 v71.12,54.29 | 72.34,54.02 71.14,53.96 v71.12,54.29 | 68.58,30.39 68.26,28.96 v68.58,28.89 | 68.58,30.39 68.9,28.96 v68.58,28.89 | 96.84,27.39 97.16,28.82 v96.84,28.89 | 96.84,27.39 96.52,28.82 v96.84,28.89
BUSY  (via drill 0.6 pad 1.27)
  Top 0.406: v17.78,58.42 16.28,58.42 | 12.93,58.42 v11.43,58.42 | 12.93,58.42 11.59,58.88 | v11.43,58.42 11.59,58.88 | 12.93,58.42 11.59,57.96 | v11.43,58.42 11.59,57.96 | 12.93,58.42 11.59,58.88 | 12.93,58.42 11.59,57.96 | 12.93,58.42 11.59,58.88 | v11.43,58.42 11.59,58.88 | 12.93,58.42 11.59,57.96 | v11.43,58.42 11.59,57.96 | 16.28,58.42 17.62,57.96 | v17.78,58.42 17.62,57.96 | 16.28,58.42 17.62,58.88 | v17.78,58.42 17.62,58.88 | 17.62,57.96 16.28,58.42 | 17.62,58.88 16.28,58.42 | 16.28,58.42 17.62,57.96 | v17.78,58.42 17.62,57.96 | 16.28,58.42 17.62,58.88 | v17.78,58.42 17.62,58.88 | 12.93,58.42 11.55,58.83 | 11.55,58.83 | 11.55,58.83 12.93,58.42 | 11.55,58.83 v11.43,58.42 | 12.93,58.42 | 11.55,58.01 12.93,58.42 | 11.55,58.01 | 11.55,58.01 v11.43,58.42 | 12.93,58.42 11.55,58.83 | 12.93,58.42 11.55,58.01 | 11.55,58.01 v11.43,58.42 | 11.55,58.83 12.93,58.42 | 11.55,58.83 v11.43,58.42 | 12.93,58.42 11.55,58.01 | v11.43,58.42 11.55,58.01 | 17.66,58.01 16.28,58.42 | 17.66,58.01 | 16.28,58.42 | 17.66,58.01 16.28,58.42 | 17.66,58.01 | v17.78,58.42 17.66,58.01 | 17.66,58.01 16.28,58.42 | v17.78,58.42 17.66,58.01 | 17.66,58.83 16.28,58.42 | 17.66,58.83 v17.78,58.42 | 17.66,58.01 16.28,58.42 | v17.78,58.42 17.66,58.01 | 17.66,58.83 16.28,58.42 | v17.78,58.42 17.66,58.83
  Top 0.61: 16.28,58.42 | 16.28,58.42 12.93,58.42 | 12.93,58.42 | 17.66,58.83 16.28,58.42
  Bottom 0.61: v17.78,58.42 16.83,57.47 16.83,57.26 | 16.83,57.26 16.83,51.44 14.92,49.53 14.92,46.04 Q6.1 15.88,45.09 15.88,42.55 R13.1 | v11.43,58.42 11.11,58.42 10.22,57.53 | X1.11 9.46,56.77 10.22,57.53 | 10.22,57.53 11.56,58.12 v11.43,58.42 | 10.22,57.53 11.18,58.64 v11.43,58.42 | 16.83,57.26 17.98,58.16 v17.78,58.42 | 16.83,57.26 17.48,58.57 v17.78,58.42
D0
  Bottom 0.61: R20.1 42.55,33.66 26.67,33.66 26.35,33.34 10.79,33.34 9.38,31.93 X1.2
D1
  Bottom 0.406: 41.27,35.56 43.81,35.56
  Bottom 0.61: 41.27,35.56 40.96,35.56 40.01,34.61 26.04,34.61 25.72,34.29 9.53,34.29 9.14,34.67 X1.3 | 43.81,35.56 44.13,35.56 45.4,34.29 R21.1
D2
  Bottom 0.61: R22.2 43.81,38.42 40.64,38.42 38.73,36.51 24.77,36.51 24.45,36.2 11.43,36.2 10.19,37.44 X1.4
D3
  Bottom 0.61: 24.13,39.05 23.18,38.1 12.7,38.1 10.59,40.21 X1.5 | 24.13,39.05 R40.2 | 24.13,39.05 24.77,38.42 36.83,38.42 37.78,39.37 37.78,40.01 39.37,41.59 R23.2
D4
  Bottom 0.61: R25.1 15.88,64.77 15.88,52.07 12.06,48.26 12.06,47.31 10.79,46.04 10.79,44.77 8.98,42.95 X1.6
D5
  Bottom 0.61: R27.2 14.92,52.7 10.79,48.58 10.79,47.62 8.89,45.72 X1.7
D6
  Bottom 0.61: R24.1 13.97,64.77 13.97,53.34 9.12,48.49 X1.8
D7
  Bottom 0.61: X1.12 9.35,59.51 9.84,60.01 12.06,60.01 13.02,59.05 13.02,54.29 12.06,53.34 R1.2 9.32,51.23 X1.9
DATA0
  Bottom 0.61: R28.2 RN1.2 40.01,72.39 42.55,74.93 46.35,74.93 47.62,73.66 IC4.14 58.74,73.66 60.01,74.93 IC6.12 78.11,74.93 79.38,73.66 87.63,73.66 89.53,71.75 89.53,67.94 95.25,62.23 95.25,37.47 96.52,36.2 IC5.20 96.52,32.38 95.25,31.11 IC2.1 95.25,26.04 93.34,24.13 92.39,24.13 90.17,21.91 IC3.1
DATA1
  Bottom 0.61: R29.1 RN1.3 40.01,69.85 43.81,73.66 IC4.15 45.72,73.66 46.99,72.39 IC6.13 78.11,72.39 79.38,71.12 86.68,71.12 87,70.8 87,67.31 92.71,61.59 92.71,37.47 93.98,36.2 IC5.19 93.98,28.57 92.71,27.3 IC2.2 92.71,26.04 90.81,24.13 89.85,24.13 87.63,21.91 IC3.2
DATA2
  Bottom 0.61: R30.2 RN1.4 40.01,67.31 43.81,71.12 IC4.16 45.72,71.12 46.99,69.85 IC6.14 78.11,69.85 79.38,68.58 84.14,68.58 91.44,61.28 91.44,52.7 89.85,51.12 89.85,49.53 90.17,49.21 90.17,37.47 91.44,36.2 IC5.18 91.44,28.57 90.17,27.3 IC2.3 90.17,26.04 88.27,24.13 87.31,24.13 85.09,21.91 IC3.3
DATA3
  Bottom 0.61: R31.1 RN1.5 40.01,64.77 43.81,68.58 IC4.17 45.4,68.58 46.67,67.31 IC6.15 78.11,67.31 79.38,66.04 85.09,66.04 90.17,60.96 90.17,53.02 87.63,50.48 87.63,37.47 88.9,36.2 IC5.17 88.9,28.57 87.63,27.3 IC2.4 87.63,26.04 85.72,24.13 84.77,24.13 82.55,21.91 IC3.4
DATA4
  Bottom 0.61: R32.2 RN1.6 40.01,62.23 43.81,66.04 IC4.18 45.72,66.04 46.99,64.77 IC6.16 78.11,64.77 79.38,63.5 86.04,63.5 88.9,60.64 88.9,53.34 85.09,49.53 85.09,38.73 81.28,34.92 IC5.14 81.28,30.48 82.87,28.89 83.5,28.89 85.09,27.3 IC2.5 85.09,26.04 83.19,24.13 82.23,24.13 80.01,21.91 IC3.5
DATA5
  Bottom 0.61: R33.1 RN1.7 39.69,59.69 43.5,63.5 IC4.19 45.72,63.5 46.99,62.23 IC6.17 78.11,62.23 79.38,60.96 87,60.96 87.63,60.33 87.63,53.66 82.55,48.58 82.55,38.73 78.74,34.92 78.74,32.38 | 78.74,32.38 IC5.13 | IC3.6 77.47,21.91 79.69,24.13 80.64,24.13 82.55,26.04 IC2.6 82.55,27.62 78.74,31.43 78.74,32.38
DATA6
  Bottom 0.61: R34.2 RN1.8 42.23,57.15 | 42.23,57.15 42.23,54.93 43.81,53.34 IC4.23 | 42.23,57.15 46.04,57.15 48.58,59.69 IC6.18 78.11,59.69 79.38,58.42 85.41,58.42 86.68,57.15 86.68,54.29 81.28,48.9 81.28,45.72 80.01,44.45 80.01,38.73 76.2,34.92 IC5.12 76.2,31.43 80.01,27.62 IC2.7 80.01,26.04 78.11,24.13 77.15,24.13 74.93,21.91 IC3.7
DATA7
  Bottom 0.61: R35.1 RN1.9 40.01,54.61 43.81,50.8 IC4.24 45.4,50.8 46.67,52.07 46.67,54.61 49.21,57.15 IC6.19 78.11,57.15 79.38,55.88 84.45,55.88 85.09,55.24 85.09,54.29 79.06,48.26 78.74,48.26 77.47,46.99 77.47,45.72 78.11,45.09 78.11,42.86 77.47,42.23 77.47,38.73 73.66,34.92 73.66,32.7 | 73.66,32.7 IC5.11 | IC3.8 72.39,21.91 74.61,24.13 75.56,24.13 77.47,26.04 IC2.8 77.47,27.3 73.66,31.11 73.66,32.7
GND  (via drill 0.6, 0.6 pad 1.27)
  Top 0.406: v99.06,30.48 97.56,30.48 | v97.79,43.18 96.29,43.18 | 85.32,43.18 v83.82,43.18 | v54.29,77.79 54.29,76.29 | 54.29,59.92 v54.29,58.42 | v97.79,24.13 96.29,24.13 | 68.81,24.13 v67.31,24.13 | 87.86,30.48 86.52,30.94 | v86.36,30.48 86.52,30.94 | 87.86,30.48 86.52,30.02 | v86.36,30.48 86.52,30.02 | 87.86,30.48 86.52,30.94 | 87.86,30.48 86.52,30.02 | 87.86,30.48 86.52,30.94 | v86.36,30.48 86.52,30.94 | 87.86,30.48 86.52,30.02 | v86.36,30.48 86.52,30.02 | 97.56,30.48 98.91,30.02 | v99.06,30.48 98.91,30.02 | 97.56,30.48 | 87.86,30.48 | 97.56,30.48 98.91,30.94 | v99.06,30.48 98.91,30.94 | 98.91,30.02 97.56,30.48 | 98.91,30.94 97.56,30.48 | 97.56,30.48 98.91,30.02 | v99.06,30.48 98.91,30.02 | 97.56,30.48 98.91,30.94 | v99.06,30.48 98.91,30.94 | 85.32,43.18 83.97,43.64 | v83.82,43.18 83.97,43.64 | 85.32,43.18 83.97,42.72 | v83.82,43.18 83.97,42.72 | 85.32,43.18 83.97,43.64 | 85.32,43.18 83.97,42.72 | 85.32,43.18 83.97,43.64 | v83.82,43.18 83.97,43.64 | 85.32,43.18 83.97,42.72 | v83.82,43.18 83.97,42.72 | 96.29,43.18 97.64,42.72 | v97.79,43.18 97.64,42.72 | 96.29,43.18 97.64,43.64 | v97.79,43.18 97.64,43.64 | 97.64,42.72 96.29,43.18 | 97.64,43.64 96.29,43.18 | 96.29,43.18 97.64,42.72 | v97.79,43.18 97.64,42.72 | 96.29,43.18 97.64,43.64 | v97.79,43.18 97.64,43.64 | 54.29,59.92 53.84,58.58 | v54.29,58.42 53.84,58.58 | 54.29,59.92 54.75,58.58 | v54.29,58.42 54.75,58.58 | 54.29,59.92 53.84,58.58 | 54.29,59.92 54.75,58.58 | 54.29,59.92 53.84,58.58 | v54.29,58.42 53.84,58.58 | 54.29,59.92 54.75,58.58 | v54.29,58.42 54.75,58.58 | 54.29,76.29 54.75,77.63 | v54.29,77.79 54.75,77.63 | 54.29,76.29 53.84,77.63 | v54.29,77.79 53.84,77.63 | 54.29,76.29 54.75,77.63 | 54.29,76.29 53.84,77.63 | 54.75,77.63 54.29,76.29
  Top 0.406: v54.29,77.79 54.75,77.63 | 53.84,77.63 54.29,76.29 | v54.29,77.79 53.84,77.63 | 68.81,24.13 67.47,24.59 | v67.31,24.13 67.47,24.59 | 68.81,24.13 67.47,23.67 | v67.31,24.13 67.47,23.67 | 68.81,24.13 67.47,24.59 | 68.81,24.13 67.47,23.67 | 68.81,24.13 67.47,24.59 | v67.31,24.13 67.47,24.59 | 68.81,24.13 67.47,23.67 | v67.31,24.13 67.47,23.67 | 96.29,24.13 97.71,23.79 | v97.79,24.13 97.71,23.79 | 96.29,24.13 97.71,24.47 | v97.79,24.13 97.71,24.47 | 97.71,23.79 96.29,24.13 | 97.71,24.47 96.29,24.13 | 96.29,24.13 97.71,23.79 | v97.79,24.13 97.71,23.79 | 96.29,24.13 97.71,24.47 | v97.79,24.13 97.71,24.47 | 87.86,30.48 86.48,30.89 | 86.48,30.89 | 86.48,30.89 87.86,30.48 | 86.48,30.89 v86.36,30.48 | 87.86,30.48 | 86.48,30.07 87.86,30.48 | 86.48,30.07 | 86.48,30.07 v86.36,30.48 | 87.86,30.48 86.48,30.89 | 87.86,30.48 86.48,30.07 | 86.48,30.07 v86.36,30.48 | 86.48,30.89 87.86,30.48 | 86.48,30.89 v86.36,30.48 | 87.86,30.48 86.48,30.07 | v86.36,30.48 86.48,30.07 | 98.94,30.07 97.56,30.48 | 98.94,30.07 | 97.56,30.48 | 98.94,30.07 97.56,30.48 | 98.94,30.07 | v99.06,30.48 98.94,30.07 | 98.94,30.89 97.56,30.48 | 98.94,30.07 97.56,30.48 | v99.06,30.48 98.94,30.07 | 98.94,30.89 97.56,30.48 | 98.94,30.89 | v99.06,30.48 98.94,30.89 | 98.94,30.07 97.56,30.48 | v99.06,30.48 98.94,30.07 | 98.94,30.89 97.56,30.48 | v99.06,30.48 98.94,30.89 | 85.32,43.18 83.94,43.59 | 83.94,43.59 | 83.94,43.59 85.32,43.18 | 83.94,43.59 v83.82,43.18 | 85.32,43.18 | 83.94,42.77 85.32,43.18 | 83.94,42.77 | 83.94,42.77 v83.82,43.18 | 85.32,43.18 83.94,43.59 | 85.32,43.18 83.94,42.77 | 83.94,42.77 v83.82,43.18 | 83.94,43.59 85.32,43.18 | 83.94,43.59 v83.82,43.18 | 85.32,43.18 83.94,42.77 | v83.82,43.18 83.94,42.77 | 97.67,42.77 96.29,43.18
  Top 0.406: 97.67,42.77 | 96.29,43.18 | 97.67,42.77 96.29,43.18 | 97.67,42.77 | v97.79,43.18 97.67,42.77 | 97.67,43.59 96.29,43.18 | 97.67,42.77 96.29,43.18 | v97.79,43.18 97.67,42.77 | 97.67,43.59 96.29,43.18 | 97.67,43.59 v97.79,43.18 | 97.67,42.77 96.29,43.18 | v97.79,43.18 97.67,42.77 | 97.67,43.59 96.29,43.18 | v97.79,43.18 97.67,43.59 | 53.88,58.54 54.29,59.92 | 53.88,58.54 | 54.29,59.92 | 54.29,59.92 53.88,58.54 | 53.88,58.54 | v54.29,58.42 53.88,58.54 | 54.71,58.54 54.29,59.92 | 54.29,59.92 53.88,58.54 | 53.88,58.54 v54.29,58.42 | 54.29,59.92 54.71,58.54 | 54.71,58.54 | 54.71,58.54 v54.29,58.42 | 54.29,59.92 53.88,58.54 | v54.29,58.42 53.88,58.54 | 54.71,58.54 54.29,59.92 | 54.71,58.54 v54.29,58.42 | 54.71,77.66 54.29,76.29 | 54.71,77.66 | 54.71,77.66 54.29,76.29 | v54.29,77.79 54.71,77.66 | 54.29,76.29 | 53.88,77.66 54.29,76.29 | 53.88,77.66 | v54.29,77.79 53.88,77.66 | 54.71,77.66 54.29,76.29 | 53.88,77.66 54.29,76.29 | v54.29,77.79 53.88,77.66 | 54.71,77.66 54.29,76.29 | v54.29,77.79 54.71,77.66 | 53.88,77.66 54.29,76.29 | v54.29,77.79 53.88,77.66 | 68.81,24.13 67.43,24.54 | 67.43,24.54 | 67.43,24.54 68.81,24.13 | 67.43,24.54 v67.31,24.13 | 68.81,24.13 | 67.43,23.72 68.81,24.13 | 67.43,23.72 | 67.43,23.72 v67.31,24.13 | 68.81,24.13 67.43,24.54 | 68.81,24.13 67.43,23.72 | 67.43,23.72 v67.31,24.13 | 67.43,24.54 68.81,24.13 | 67.43,24.54 v67.31,24.13 | 68.81,24.13 67.43,23.72 | v67.31,24.13 67.43,23.72 | 96.29,24.13 | 97.73,23.84 96.29,24.13 | 97.73,23.84 | 97.73,23.84 | v97.79,24.13 97.73,23.84 | 97.73,24.42 96.29,24.13 | 97.73,23.84 96.29,24.13 | v97.79,24.13 97.73,23.84 | 97.73,24.42 96.29,24.13 | 97.73,24.42 | v97.79,24.13 97.73,24.42 | 97.73,23.84 96.29,24.13 | v97.79,24.13 97.73,23.84 | 97.73,24.42 96.29,24.13
  Top 0.406: v97.79,24.13 97.73,24.42
  Top 0.61: v86.36,30.48 87.86,30.48 97.56,30.48 | 96.29,43.18 | 96.29,43.18 85.32,43.18 | 85.32,43.18 | 54.29,76.29 | 54.29,76.29 54.29,59.92 | 54.29,59.92 | 96.29,24.13 | 96.29,24.13 68.81,24.13 | 68.81,24.13
  Bottom 0.406: 26.99,29.21 29.53,29.21
  Bottom 0.61: IC4.22 46.35,55.88 48.9,58.42 IC4.8 52.79,58.42 | v86.36,30.48 86.36,31.98 | 86.36,31.98 IC5.16 | 100.01,30.48 v99.06,30.48 | v83.82,43.18 83.82,41.68 | 83.82,41.68 IC5.6 | 100.01,43.18 99.29,43.18 | 99.29,43.18 v97.79,43.18 | 100.01,30.48 100.01,31.64 | 100.01,31.64 100.01,43.18 | 100.01,24.13 100.01,0 76.2,0 | 100.01,24.13 100.01,29.32 | 100.01,29.32 100.01,30.48 | 82.55,80.01 IC6.10 | 82.55,80.01 100.01,80.01 100.01,43.18 | v54.29,58.42 52.79,58.42 | 54.29,80.01 54.29,79.29 | 54.29,79.29 v54.29,77.79 | 82.55,80.01 54.29,80.01 | 54.29,80.01 29.21,80.01 | 8.26,80.01 8.26,78.11 19.37,66.99 19.37,62.23 23.5,62.23 24.13,61.59 24.13,58.42 | 8.26,80.01 29.21,80.01 | 10.16,0 0,0 0,9.21 | 10.16,0 15.56,0 | 15.56,0 28.57,0 | 28.57,0 45.72,0 | 45.72,0 76.2,0 | 29.21,80.01 IC1.10 C6.2 | 0,60.96 0,69.22 | 0,69.22 0,80.01 8.26,80.01 | 28.89,20.32 28.57,20.32 | C1.2 31.11,19.05 29.84,20.32 IC11.4 28.89,20.32 | 24.13,58.42 IC1.18 21.91,58.42 | 24.13,58.42 IC1.3 | 0,9.21 0,13.97 | 0,13.97 0,22.23 | 0,22.23 0,41.59 | 0,41.59 0,44.13 | 0,44.13 0,46.99 | 0,46.99 0,49.85 | 0,49.85 0,52.7 | 0,52.7 0,55.24 | 0,55.24 0,58.1 | 0,58.1 0,60.96 | 0,13.97 2.22,13.97 | X2.C 0.14,9.07 0,9.21 | 2.22,13.97 X2.- | 2.22,13.97 2.22,15.24 4.76,17.78 8.89,17.78 11.87,20.77 C2.- 11.87,25.21 13.97,27.3 20.95,27.3 21.59,26.67 R17.2 24.13,25.4 | C4.- 10.29,0.13 10.16,0 | Q6.3 12.06,42.55 12.06,41.91 | 12.06,41.91 12.06,40.32 13.34,39.05 20,39.05 20.95,40.01 20.95,44.45 22.23,45.72 R11.2 | 12.06,41.91 10.48,41.91 10.15,41.58 X1.18 5.08,41.59 0,41.59 | 24.13,58.42 23.5,58.42 | R11.2 R41.2 Q3.1 | R8.1 Q2.1 | 24.13,25.4 25.08,24.45 25.08,20.32 | IC11.2 27.62,15.24 25.08,17.78 25.08,20.32
  Bottom 0.61: 25.08,20.32 28.89,20.32 | 24.13,25.4 24.13,26.67 R3.2 25.72,27.94 26.99,29.21 | Q1.1 30.48,30.16 29.53,29.21 | 76.2,0 RN2.1 IC7.14 76.2,13.02 75.72,13.49 73.5,13.49 72.39,12.38 IC2.31 | IC2.11 69.85,26.35 68.52,25.02 | v67.31,24.13 67.63,24.13 68.52,25.02 | 100.01,24.13 99.29,24.13 | 99.29,24.13 v97.79,24.13 | IC10.GND 13.97,13.97 15.56,12.38 15.56,0 | R6.2 40.96,24.13 41.91,23.18 IC3.20 41.91,21.27 40.96,20.32 38.73,20.32 36.51,18.1 36.51,15.24 40.32,11.43 44.13,11.43 45.72,9.84 IC8.4 45.72,0 | LED1.K 28.7,8.13 C3.- 28.7,0.13 28.57,0 | R8.1 C5.2 | R11.2 R8.1 | X1.25 0.05,60.91 0,60.96 | X1.24 0.04,58.14 0,58.1 | X1.23 0.13,55.37 0,55.24 | X1.22 0.08,52.63 0,52.7 | X1.21 0.01,49.86 0,49.85 | X1.20 0.1,47.09 0,46.99 | X1.19 0.22,44.35 0,44.13 | X1.G2 0.03,69.24 0,69.22 | X1.G1 0.03,22.2 0,22.23 | 86.36,31.98 86.04,30.55 v86.36,30.48 | 86.36,31.98 86.68,30.55 v86.36,30.48 | 100.01,31.64 98.86,30.74 v99.06,30.48 | 100.01,31.64 99.36,30.33 v99.06,30.48 | 100.01,29.32 99.36,30.63 v99.06,30.48 | 100.01,29.32 98.86,30.22 v99.06,30.48 | 83.82,41.68 84.14,43.11 v83.82,43.18 | 83.82,41.68 83.5,43.11 v83.82,43.18 | 99.29,43.18 97.86,43.5 v97.79,43.18 | 99.29,43.18 97.86,42.86 v97.79,43.18 | 52.79,58.42 54.22,58.1 v54.29,58.42 | 52.79,58.42 54.22,58.74 v54.29,58.42 | 54.29,79.29 53.97,77.86 v54.29,77.79 | 54.29,79.29 54.62,77.86 v54.29,77.79 | 68.52,25.02 67.18,24.43 v67.31,24.13 | 68.52,25.02 67.56,23.91 v67.31,24.13 | 99.29,24.13 97.82,24.33 v97.79,24.13 | 99.29,24.13 97.82,23.93 v97.79,24.13
  pour Bottom (isolate 0.61): 0,80.01 100.01,80.01 100.01,0 0,0
  pour Top (isolate 1.016, no thermals): 0,80.01 100.01,80.01 100.01,0 0,0
N$1
  Bottom 0.61: R26.2 19.05,59.05 20.95,60.96 IC1.17
N$2
  Bottom 0.61: RN2.2 IC7.13
N$3
  Bottom 0.61: IC1.12 14.29,73.66 12.7,75.25 R24.2
N$4
  Bottom 0.61: IC1.19 21.27,55.88 19.05,53.66 R1.1
N$5
  Bottom 0.61: R28.1 30.48,68.58 IC1.7
N$6
  Bottom 0.61: R29.2 33.66,69.85 31.11,67.31 27.94,67.31 24.13,71.12 IC1.13
N$7
  Bottom 0.61: R30.1 33.97,67.31 32.7,66.04 IC1.6
N$8
  Bottom 0.61: R31.2 27.94,64.77 24.13,68.58 IC1.14
N$9
  Bottom 0.61: R15.2 19.68,11.43 20.95,12.7 IC11.8
N$10
  Bottom 0.61: IC1.5 33.02,63.5 R32.1
N$11
  Bottom 0.61: IC11.3 29.84,17.78 31.11,16.51 C1.1
N$12
  Bottom 0.61: R14.2 19.05,15.88 19.68,15.24 | 19.68,15.24 IC11.7 22.54,15.24 23.81,13.97 23.81,11.43 18.73,6.35 18.73,5.71 L1.1 | R15.1 19.05,14.61 19.68,15.24
N$13
  Bottom 0.61: D1.A 31.11,11.43 29.84,12.7 IC11.1 25.72,12.7 25.08,12.06 25.08,10.79 23.5,9.21 23.5,6.35 23.81,6.03 23.77,5.99 L1.2
N$14
  Bottom 0.61: R4.1 26.67,26.67 Q1.3
N$15
  Bottom 0.61: Q4.2 R5.1 R4.2
N$16
  Bottom 0.61: R2.2 R3.1 Q1.2
N$17
  Bottom 0.61: IC11.5 21.59,21.27 21.27,21.59 | R16.2 21.27,21.59 | R17.1 21.59,21.91 21.27,21.59
N$18
  Bottom 0.61: JP2.3 38.1,3.81 40.64,6.35 IC8.2
N$19
  Bottom 0.61: R9.2 R10.1 Q5.2
N$20
  Bottom 0.61: Q6.2 14.61,43.81 14.61,41.27 R12.1
N$21
  Bottom 0.61: IC1.15 24.13,66.04 27.94,62.23 31.43,62.23 33.97,59.69 R33.2
N$22
  Bottom 0.61: R9.1 Q2.3 28.57,50.8 26.99,52.39 26.99,54.29 28.57,55.88 IC1.2
N$23
  Bottom 0.61: Q2.2 26.67,50.8 R8.2 | R8.2 23.81,50.8 | R8.2 20.95,50.8 19.05,48.9 19.05,47.94 19.68,47.31 19.68,41.27 R7.2
N$24
  Bottom 0.61: IC1.4 31.11,60.96 32.7,59.37 32.7,58.74 R34.1
N$25
  Bottom 0.61: IC1.16 23.81,63.5 27.62,59.69 30.8,59.69 31.75,58.74 31.75,58.1 32.7,57.15 32.7,56.2 R35.2
N$26
  Bottom 0.61: RN2.3 IC7.12
N$27
  Bottom 0.61: RN2.4 IC7.11
N$28
  Bottom 0.61: JP1.2 R39.1
N$29
  Bottom 0.61: Q3.3 R39.2
N$30
  Bottom 0.61: R40.1 R41.1 Q3.2
N$31
  Bottom 0.61: JP2.1 IC8.3
N$32
  Bottom 0.61: R36.2 30.48,8.89 LED1.A
PAGEL  (via drill 0.5 pad 1.27, 0.6 pad 1.27)
  Top 0.406: v56.2,58.42 56.2,59.67 | 56.2,69.87 v56.2,71.12 | v56.2,40.01 56.2,41.51 | 56.2,57.17 v56.2,58.42 | 56.2,69.87 56.64,70.93 v56.2,71.12 | 56.2,69.87 55.75,70.93 v56.2,71.12 | 56.2,69.87 56.64,70.93 | 56.2,69.87 55.75,70.93 | 56.2,69.87 56.64,70.93 | v56.2,71.12 56.64,70.93 | 56.2,69.87 55.75,70.93 | v56.2,71.12 55.75,70.93 | 56.2,59.67 55.75,58.61 | v56.2,58.42 55.75,58.61 | 56.2,59.67 56.64,58.61 | v56.2,58.42 56.64,58.61 | 56.2,57.17 56.64,58.23 v56.2,58.42 | 56.2,57.17 55.75,58.23 v56.2,58.42 | 55.75,58.61 56.2,59.67 | 56.64,58.61 56.2,59.67 | 56.2,59.67 55.75,58.61 | v56.2,58.42 55.75,58.61 | 56.2,59.67 56.64,58.61 | v56.2,58.42 56.64,58.61 | 56.2,57.17 56.64,58.23 | 56.2,57.17 55.75,58.23 | 56.2,57.17 56.64,58.23 | v56.2,58.42 56.64,58.23 | 56.2,57.17 55.75,58.23 | v56.2,58.42 55.75,58.23 | 56.2,41.51 55.74,40.16 | v56.2,40.01 55.74,40.16 | 56.2,41.51 56.65,40.16 | v56.2,40.01 56.65,40.16 | 55.74,40.16 56.2,41.51 | 56.65,40.16 56.2,41.51 | 56.2,41.51 55.74,40.16 | v56.2,40.01 55.74,40.16 | 56.2,41.51 56.65,40.16 | v56.2,40.01 56.65,40.16 | 56.6,70.97 56.2,69.87 | 56.2,69.87 | 55.79,70.97 56.2,69.87 | 56.2,69.87 56.6,70.97 | 56.6,70.97 v56.2,71.12 | 56.2,69.87 55.79,70.97 | 55.79,70.97 v56.2,71.12 | 56.2,69.87 56.6,70.97 | v56.2,71.12 56.6,70.97 | 56.2,69.87 55.79,70.97 | v56.2,71.12 55.79,70.97 | 56.2,59.67 | 55.79,58.57 56.2,59.67 | 55.79,58.57 | v56.2,58.42 55.79,58.57 | 56.6,58.57 56.2,59.67 | 56.6,58.57 | v56.2,58.42 56.6,58.57 | 55.79,58.57 56.2,59.67 | 56.6,58.57 56.2,59.67 | 55.79,58.57 56.2,59.67 | v56.2,58.42 55.79,58.57 | 56.6,58.57 56.2,59.67 | v56.2,58.42 56.6,58.57 | 56.6,58.27 56.2,57.17 | 56.2,57.17 | 55.79,58.27 56.2,57.17 | 56.2,57.17 56.6,58.27 | 56.6,58.27 v56.2,58.42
